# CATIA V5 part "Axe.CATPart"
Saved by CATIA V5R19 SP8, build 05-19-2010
Part number: Axe_moteur_droit
Bounding box of the stored display mesh (mm): x -20 to 20, y -20 to 20, z -240 to 90
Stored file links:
  G:\EU_thinkMotion\CFAO_2010\MMS_groupe1\MMS_groupe1\OK\vduret\vduret\CATIA\Axe.CATPart
  F:\CFAO_TP_fin\Machine_de_coupe_sans_geo.CATProduct
  G:\EU_thinkMotion\CFAO_2010\MMS_groupe1\MMS_groupe1\OK\vduret\vduret\CATIA\Entretoise_50.CATPart
  G:\EU_thinkMotion\CFAO_2010\MMS_groupe1\MMS_groupe1\OK\vduret\vduret\CATIA\Disque_porteur.CATPart
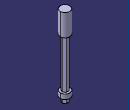
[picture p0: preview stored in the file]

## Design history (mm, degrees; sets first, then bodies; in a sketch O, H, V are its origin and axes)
Parameters
  Longueur_axe_couronne = 200 mm
Body1 (main body)
  Sketch1 on xy-plane, origin (0, 0, 0), H (1, 0, 0), V (0, 1, 0)
    circle A1 centre (0, 0) radius 20
    radius A1 = 20
  Pad1: profile Sketch1, direction (0, 0, 1), length 90
  Sketch2 on start face of Pad1, origin (0, 0, 0), H (1, 0, 0), V (0, -1, 0)
    point P1 (0, 0)
    point P2 (6.3509, -11)
    point P3 (12.7017, 0)
    point P4 (6.3509, 11)
    point P5 (-6.3509, 11)
    point P6 (-12.7017, 0)
    point P7 (-6.3509, -11)
    point P8 (9.5263, -5.5)
    line L1 (6.3509, -11) -> (12.7017, 0)
    line L2 (12.7017, 0) -> (6.3509, 11)
    line L3 (6.3509, 11) -> (-6.3509, 11)
    line L4 (-6.3509, 11) -> (-12.7017, 0)
    line L5 (-12.7017, 0) -> (-6.3509, -11)
    line L6 (-6.3509, -11) -> (6.3509, -11)
    construction line L7 (0, 0) -> (9.5263, -5.5)
    construction circle A1 centre (0, 0) radius 12.7017
    construction arc A2 centre (-12.7017, 0) radius 12.7017 from (-6.3509, 11) to (-6.3509, -11) cw
    construction arc A3 centre (12.7017, 0) radius 12.7017 from (6.3509, 11) to (6.3509, -11) ccw
    reference projected circle E1 centre (0, 0) radius 20 from edge [start face of Pad1 | face of Pad1 from Sketch1.A1]
    distance L3 L6 = 22
    coincidence: A1 P2, A1 P3, A1 P4, A1 P5, A1 P6, A1 P7, A2 P1, A3 P1
    midpoint: P8 L1
    parallelism: L1 L4
    concentricity: P1 E1
    horizontal: L6 H
  Pad2: profile Sketch2, direction (0, 0, -1), length 200 {= Longueur_axe_couronne}
  Sketch3 on end face of Pad2, origin (0, 0, -200), H (1, 0, 0), V (0, -1, 0)
    circle A1 centre (0, 0) radius 20
    radius A1 = 20
  Pad3: profile Sketch3, direction (0, 0, -1), length 20
  Sketch4 on end face of Pad3, origin (0, 0, -220), H (1, 0, 0), V (0, -1, 0)
    point P1 (6.3509, -11)
    point P2 (12.7017, 0)
    point P3 (6.3509, 11)
    point P4 (-6.3509, 11)
    point P5 (-12.7017, 0)
    point P6 (-6.3509, -11)
    point P7 (9.5263, -5.5)
    line L1 (6.3509, -11) -> (12.7017, 0)
    line L2 (12.7017, 0) -> (6.3509, 11)
    line L3 (6.3509, 11) -> (-6.3509, 11)
    line L4 (-6.3509, 11) -> (-12.7017, 0)
    line L5 (-12.7017, 0) -> (-6.3509, -11)
    line L6 (-6.3509, -11) -> (6.3509, -11)
    construction line L7 (0, 0) -> (9.5263, -5.5)
    construction circle A1 centre (0, 0) radius 12.7017
    construction arc A2 centre (-12.7017, 0) radius 12.7017 from (-6.3509, 11) to (-6.3509, -11) cw
    construction arc A3 centre (12.7017, 0) radius 12.7017 from (6.3509, 11) to (6.3509, -11) ccw
    distance L2 L5 = 22
    coincidence: A1 P1, A1 P2, A1 P3, A1 P4, A1 P5, A1 P6, A2 O, A3 O
    midpoint: P7 L1
    parallelism: L1 L4
    horizontal: L6 H
  Pad4: profile Sketch4, direction (0, 0, -1), length 20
